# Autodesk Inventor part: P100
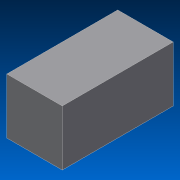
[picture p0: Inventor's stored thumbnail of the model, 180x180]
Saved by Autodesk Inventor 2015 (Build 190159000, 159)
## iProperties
Created: 2017-11
Part Number: P100
Material: Všeobecné
Document SubType Name: Modeling
Designer: navara
Mass: 2 g
Surface Area: 10 cm^2
Volume: 2 cm^3
Density: 1 g/cm^3
Appearance: Výchozí
Title: 112233
Author: navara
Last Saved By: navara
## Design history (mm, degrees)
sketch "Náčrt1"
  geometry: L1 (-5, 5)-(5, 5); L2 (5, 5)-(5, -5); L3 (5, -5)-(-5, -5); L4 (-5, -5)-(-5, 5); L5 (-5, 5)-(5, -5); L6 (5, 5)-(-5, -5); 1 further point
  constraints: 12 end point, 2 midpoint, 2 parallel, 1 horizontal, 1 perpendicular
  dimensions: "d0" = 10 distance of L2.end L3.end; "d1" = 10 distance of L1.end L2.end
extrude "Vysunutí1" new body sketch "Náčrt1" distance "d2" = 20; taper "d3" = 0 deg
node "Těleso1"
